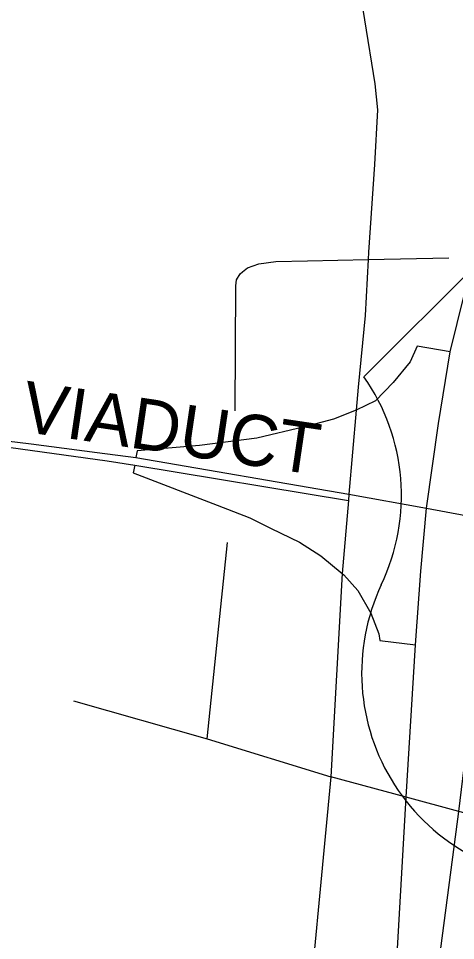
# Model space of a CAD drawing. Extents: x -8.2 to 38.5, y -0.1 to 21.9.
# Drawn here: x 5.7059 to 5.868, y 15.5938 to 15.9359 of the extents above; entities that cross this region are included whole.
import ezdxf

# ---------------------------------------------------------------- set-up
doc = ezdxf.new("R2010")
doc.units = 0
for name, color, linetype in [('GM_X_Interstate_Location', 7, 'Continuous'), ('GM_X_Major_Lake', 7, 'Continuous'), ('GM_X_State_Location', 7, 'Continuous'), ('GM_X_Township_Subdivision', 7, 'Continuous'), ('GM_X_Township_Subdivision_Text', 7, 'Continuous'), ('GM_X_Township_Text', 7, 'Continuous')]:
    doc.layers.add(name, color=color, linetype=linetype)

msp = doc.modelspace()

# ---------------------------------------------------------------- linework, layer by layer
at = {"layer": 'GM_X_Interstate_Location'}
for points in [[(5.865972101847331, 15.812134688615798), (5.853808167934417, 15.814253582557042), (5.851136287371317, 15.808468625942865), (5.844823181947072, 15.800769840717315), (5.83831121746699, 15.794065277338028), (5.831121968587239, 15.790573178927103), (5.822696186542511, 15.787236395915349), (5.812008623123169, 15.784390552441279), (5.794312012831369, 15.780121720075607), (5.773011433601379, 15.777480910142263), (5.749871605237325, 15.775504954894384), (5.749461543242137, 15.772944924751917)], [(5.74900791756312, 15.770080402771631), (5.748436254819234, 15.767340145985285), (5.779591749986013, 15.755341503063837), (5.79165877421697, 15.750575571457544), (5.799568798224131, 15.746636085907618), (5.810113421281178, 15.741516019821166), (5.817998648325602, 15.736439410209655), (5.825977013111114, 15.72997094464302), (5.82661082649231, 15.729449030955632), (5.831830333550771, 15.723664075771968), (5.83662107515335, 15.715225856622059), (5.839522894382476, 15.70758302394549), (5.839932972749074, 15.70510995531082), (5.853189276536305, 15.703506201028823)]]:
    msp.add_lwpolyline(points, dxfattribs=at)
at = {"layer": 'GM_X_State_Location'}
for points in [[(5.84568004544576, 15.57553504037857), (5.849718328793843, 15.646964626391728), (5.853189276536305, 15.703506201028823), (5.855200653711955, 15.730830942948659), (5.85720708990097, 15.754134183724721), (5.861690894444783, 15.785541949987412), (5.865972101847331, 15.812134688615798), (5.873820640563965, 15.84378978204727), (5.881649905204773, 15.877879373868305), (5.895029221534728, 15.918236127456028), (5.900402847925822, 15.934246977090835), (5.911917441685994, 15.963198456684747), (5.923432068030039, 15.989408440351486), (5.9455845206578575, 16.04138916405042), (5.968437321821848, 16.098399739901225), (5.984384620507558, 16.14328213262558), (5.999180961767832, 16.18569846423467), (6.007072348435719, 16.217921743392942), (6.012662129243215, 16.2488297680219), (6.016114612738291, 16.28269709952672)], [(5.861841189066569, 15.414176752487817), (5.858899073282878, 15.431466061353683), (5.8551689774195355, 15.465658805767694), (5.854510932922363, 15.497023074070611), (5.856923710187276, 15.525973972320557), (5.860871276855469, 15.577735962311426), (5.869280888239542, 15.64168609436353), (5.876420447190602, 15.70069574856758), (5.881375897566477, 15.727151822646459), (5.883080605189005, 15.73668036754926)]]:
    msp.add_lwpolyline(points, dxfattribs=at)
at = {"layer": 'GM_X_Township_Subdivision'}
msp.add_line((5.888976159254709, 15.857873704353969), (5.834044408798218, 15.802941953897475), dxfattribs=at)
for centre, radius, start, end in [((5.7710486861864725, 15.758830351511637), 0.07690445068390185, 334.5471236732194, 35.000929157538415), ((5.9100921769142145, 15.693073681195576), 0.07690445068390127, 154.8319194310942, 270.63826363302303)]:
    msp.add_arc(centre, radius, start, end, dxfattribs=at)
at = {"layer": 'GM_X_Township_Subdivision_Text'}
msp.add_line((5.775826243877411, 15.668629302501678), (5.783400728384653, 15.741472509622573), dxfattribs=at)
for points in [[(5.786227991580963, 15.79033703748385), (5.786451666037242, 15.836666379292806), (5.786780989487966, 15.838897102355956), (5.788061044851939, 15.841127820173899), (5.788986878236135, 15.84188592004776), (5.790844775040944, 15.843395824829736), (5.79509491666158, 15.844787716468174), (5.801370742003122, 15.845719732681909), (5.8131457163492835, 15.845955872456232), (5.835620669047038, 15.846415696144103), (5.865489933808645, 15.847024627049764)], [(5.7262968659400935, 15.682678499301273), (5.775826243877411, 15.668629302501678), (5.821745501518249, 15.654511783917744)]]:
    msp.add_lwpolyline(points, dxfattribs=at)
at = {"layer": 'GM_X_Township_Text'}
for points in [[(5.774564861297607, 16.30658984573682), (5.793964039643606, 16.182247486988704), (5.81385409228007, 16.06222989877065), (5.8304633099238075, 15.959206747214), (5.8380253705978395, 15.911690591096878), (5.839013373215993, 15.901990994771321), (5.837932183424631, 15.881709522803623), (5.835769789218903, 15.849230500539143), (5.835620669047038, 15.846415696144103), (5.834514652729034, 15.825680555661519), (5.831842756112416, 15.799054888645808), (5.831121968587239, 15.790573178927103), (5.828474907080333, 15.759355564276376), (5.828276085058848, 15.757075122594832), (5.825977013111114, 15.72997094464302), (5.821745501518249, 15.654511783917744), (5.801209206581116, 15.438355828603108)], [(5.350579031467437, 15.753269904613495), (5.362267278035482, 15.752240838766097), (5.398959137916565, 15.756975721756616), (5.412430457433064, 15.762474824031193), (5.417016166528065, 15.763102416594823), (5.538245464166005, 15.774336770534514), (5.592099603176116, 15.779270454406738), (5.624454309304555, 15.781439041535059), (5.646158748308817, 15.781240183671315), (5.682353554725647, 15.779487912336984), (5.738773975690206, 15.771758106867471), (5.74900791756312, 15.770080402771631), (5.828276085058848, 15.757075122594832)], [(5.394471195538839, 15.762971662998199), (5.412169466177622, 15.764684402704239), (5.538636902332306, 15.775899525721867), (5.591730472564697, 15.780264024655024), (5.625345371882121, 15.782479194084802), (5.656223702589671, 15.78247922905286), (5.687102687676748, 15.780915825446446), (5.710630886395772, 15.778114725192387), (5.73504946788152, 15.77479222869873), (5.749461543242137, 15.772944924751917), (5.828474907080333, 15.759355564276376)], [(5.828474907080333, 15.759355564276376), (5.85720708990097, 15.754134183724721), (5.871843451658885, 15.751474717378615), (5.88529670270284, 15.74906752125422)], [(6.013021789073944, 15.566476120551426), (5.9906648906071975, 15.57479626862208), (5.9895961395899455, 15.575125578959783), (5.981785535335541, 15.57820758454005), (5.976236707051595, 15.580879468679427), (5.973974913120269, 15.582731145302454), (5.970892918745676, 15.585403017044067), (5.965841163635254, 15.591796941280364), (5.958465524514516, 15.60112368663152), (5.949977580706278, 15.60892811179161), (5.947560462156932, 15.611065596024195), (5.944795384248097, 15.613153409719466), (5.940594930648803, 15.61588120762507), (5.901026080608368, 15.633093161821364), (5.875817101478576, 15.639915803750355), (5.869280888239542, 15.64168609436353), (5.849718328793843, 15.646964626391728), (5.821745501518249, 15.654511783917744)]]:
    msp.add_lwpolyline(points, dxfattribs=at)

# ---------------------------------------------------------------- texts
at = {"layer": 'GM_X_Major_Lake'}
msp.add_text('VIADUCT', height=0.018939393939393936, rotation=351.565424, dxfattribs=at).set_placement((5.706254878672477, 15.782750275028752))

doc.saveas('drawing.dxf')
